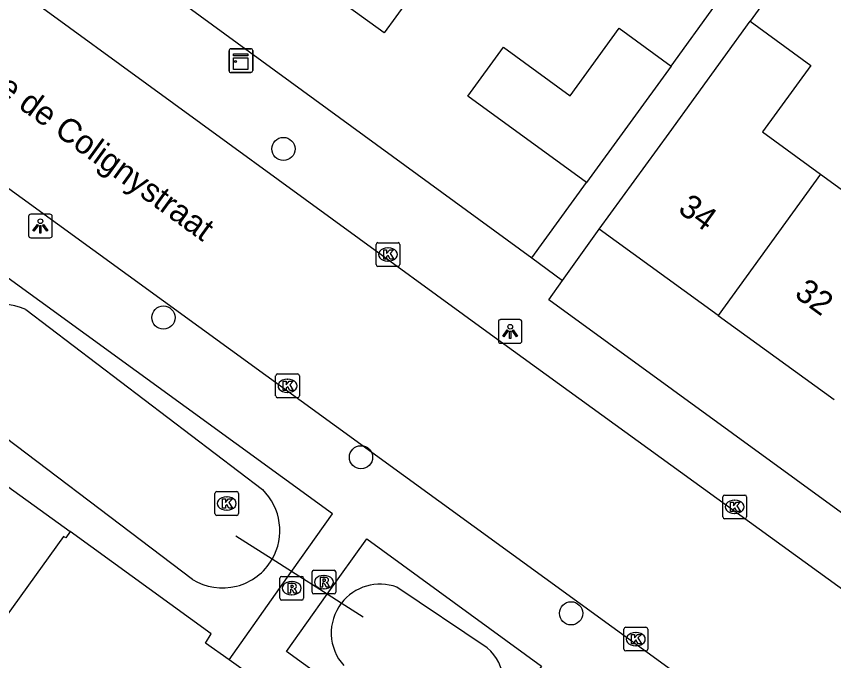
# Model space of a CAD drawing. Extents: x 159675 to 160530, y 382179 to 382901.
# Drawn here: x 160066.08 to 160100.56, y 382498.01 to 382525.17 of the extents above; entities that cross this region are included whole.
import ezdxf

# ---------------------------------------------------------------- set-up
doc = ezdxf.new("R2010")
doc.units = 0
for name, color, linetype in [('IMGEO_Boom', 7, 'Continuous'), ('IMGEO_Duiker', 7, 'Continuous'), ('IMGEO_Groenvoorziening', 7, 'Continuous'), ('IMGEO_Kast', 7, 'Continuous'), ('IMGEO_Kolk', 7, 'Continuous'), ('IMGEO_Lichtpunt', 7, 'Continuous'), ('IMGEO_Openbare_ruimte_label', 7, 'Continuous'), ('IMGEO_Pand', 7, 'Continuous'), ('IMGEO_Pand_nummerreeks', 7, 'Continuous'), ('IMGEO_Rijbaan_lokaal_open', 7, 'Continuous'), ('IMGEO_Rioolput', 7, 'Continuous'), ('IMGEO_Voetpad_open', 7, 'Continuous'), ('IMGEO_Waterloop', 7, 'Continuous')]:
    doc.layers.add(name, color=color, linetype=linetype)

msp = doc.modelspace()

# ---------------------------------------------------------------- linework, layer by layer
at = {"layer": 'IMGEO_Boom'}
for centre in [(160077.349, 382519.584), (160072.286, 382512.476), (160080.62, 382506.587), (160089.484, 382500.008)]:
    msp.add_circle(centre, 0.489, dxfattribs=at)
at = {"layer": 'IMGEO_Duiker'}
msp.add_lwpolyline([(160080.718, 382499.843), (160079.79, 382500.433), (160079.195, 382500.811), (160077.687, 382501.769), (160076.871, 382502.286), (160075.343, 382503.258)], dxfattribs=at)
at = {"layer": 'IMGEO_Groenvoorziening'}
msp.add_lwpolyline([(160075.053, 382498.052), (160074.062, 382498.749), (160074.3, 382499.148), (160068.355, 382503.451)], dxfattribs=at)
at = {"layer": 'IMGEO_Kast'}
for p, q in [((160075.052, 382522.883), (160075.052, 382523.724)), ((160075.052, 382523.724), (160075.052, 382522.883)), ((160075.127, 382523.808), (160075.968, 382523.808)), ((160075.968, 382523.808), (160075.127, 382523.808)), ((160076.052, 382523.733), (160076.052, 382522.892)), ((160076.052, 382522.892), (160076.052, 382523.733)), ((160075.977, 382522.808), (160075.136, 382522.808)), ((160075.136, 382522.808), (160075.977, 382522.808))]:
    msp.add_line(p, q, dxfattribs=at)
for points in [[(160075.247, 382523.598), (160075.847, 382523.598), (160075.847, 382523.513), (160075.247, 382523.513), (160075.247, 382523.598)], [(160075.247, 382523.423), (160075.847, 382523.423), (160075.847, 382522.934), (160075.247, 382522.934), (160075.247, 382523.423)]]:
    msp.add_lwpolyline(points, dxfattribs=at)
msp.add_circle((160075.331, 382523.272), 0.0377, dxfattribs=at)
for centre, start, end in [((160075.13, 382523.73), 92.4484, 184.2845), ((160075.13, 382523.73), 92.4484, 184.2845), ((160075.974, 382523.73), 2.4484, 94.2845), ((160075.974, 382523.73), 2.4484, 94.2845), ((160075.13, 382522.886), 182.4484, 274.2845), ((160075.13, 382522.886), 182.4484, 274.2845), ((160075.974, 382522.886), 272.4484, 4.2845), ((160075.974, 382522.886), 272.4484, 4.2845)]:
    msp.add_arc(centre, 0.0779, start, end, dxfattribs=at)
at = {"layer": 'IMGEO_Kolk'}
for p, q in [((160081.258, 382514.708), (160081.258, 382515.56)), ((160081.333, 382515.634), (160082.185, 382515.634)), ((160081.746, 382515.414), (160081.771, 382515.414)), ((160082.259, 382515.56), (160082.259, 382514.708)), ((160081.769, 382514.854), (160081.744, 382514.854)), ((160082.185, 382514.634), (160081.333, 382514.634)), ((160077.02, 382509.172), (160077.02, 382510.024)), ((160077.095, 382510.098), (160077.947, 382510.098)), ((160078.021, 382510.024), (160078.021, 382509.172)), ((160077.508, 382509.878), (160077.533, 382509.878)), ((160077.531, 382509.318), (160077.506, 382509.318)), ((160077.947, 382509.098), (160077.095, 382509.098)), ((160074.457, 382504.212), (160074.457, 382505.064)), ((160074.532, 382505.138), (160075.384, 382505.138)), ((160075.458, 382505.064), (160075.458, 382504.212)), ((160074.945, 382504.918), (160074.97, 382504.918)), ((160095.883, 382504.07), (160095.883, 382504.922)), ((160095.958, 382504.996), (160096.81, 382504.996)), ((160096.371, 382504.776), (160096.396, 382504.776)), ((160096.884, 382504.922), (160096.884, 382504.07)), ((160075.384, 382504.138), (160074.532, 382504.138)), ((160074.968, 382504.358), (160074.943, 382504.358)), ((160096.394, 382504.216), (160096.369, 382504.216)), ((160096.81, 382503.996), (160095.958, 382503.996)), ((160091.712, 382498.495), (160091.712, 382499.347)), ((160091.787, 382499.421), (160092.639, 382499.421)), ((160092.2, 382499.201), (160092.225, 382499.201)), ((160092.713, 382499.347), (160092.713, 382498.495)), ((160092.223, 382498.641), (160092.198, 382498.641)), ((160092.639, 382498.421), (160091.787, 382498.421))]:
    msp.add_line(p, q, dxfattribs=at)
for points in [[(160081.258, 382514.708), (160081.258, 382515.56)], [(160081.333, 382515.634), (160082.185, 382515.634)], [(160082.259, 382515.56), (160082.259, 382514.708)], [(160081.579, 382515.334), (160081.702, 382515.334), (160081.702, 382515.183), (160081.832, 382515.334), (160081.996, 382515.334), (160081.85, 382515.183), (160082.003, 382514.934), (160081.851, 382514.934), (160081.766, 382515.098), (160081.702, 382515.031), (160081.702, 382514.934), (160081.579, 382514.934), (160081.579, 382515.334)], [(160082.185, 382514.634), (160081.333, 382514.634)], [(160077.02, 382509.172), (160077.02, 382510.024)], [(160077.095, 382510.098), (160077.947, 382510.098)], [(160078.021, 382510.024), (160078.021, 382509.172)], [(160077.341, 382509.798), (160077.464, 382509.798), (160077.464, 382509.647), (160077.594, 382509.798), (160077.758, 382509.798), (160077.612, 382509.647), (160077.765, 382509.398), (160077.613, 382509.398), (160077.528, 382509.562), (160077.464, 382509.495), (160077.464, 382509.398), (160077.341, 382509.398), (160077.341, 382509.798)], [(160077.947, 382509.098), (160077.095, 382509.098)], [(160074.457, 382504.212), (160074.457, 382505.064)], [(160074.532, 382505.138), (160075.384, 382505.138)], [(160075.458, 382505.064), (160075.458, 382504.212)], [(160074.778, 382504.838), (160074.901, 382504.838), (160074.901, 382504.687), (160075.031, 382504.838), (160075.195, 382504.838), (160075.049, 382504.687), (160075.202, 382504.438), (160075.05, 382504.438), (160074.965, 382504.602), (160074.901, 382504.535), (160074.901, 382504.438), (160074.778, 382504.438), (160074.778, 382504.838)], [(160095.883, 382504.07), (160095.883, 382504.922)], [(160095.958, 382504.996), (160096.81, 382504.996)], [(160096.884, 382504.922), (160096.884, 382504.07)], [(160096.204, 382504.696), (160096.327, 382504.696), (160096.327, 382504.545), (160096.457, 382504.696), (160096.621, 382504.696), (160096.475, 382504.545), (160096.628, 382504.296), (160096.476, 382504.296), (160096.391, 382504.46), (160096.327, 382504.393), (160096.327, 382504.296), (160096.204, 382504.296), (160096.204, 382504.696)], [(160075.384, 382504.138), (160074.532, 382504.138)], [(160096.81, 382503.996), (160095.958, 382503.996)], [(160091.712, 382498.495), (160091.712, 382499.347)], [(160091.787, 382499.421), (160092.639, 382499.421)], [(160092.713, 382499.347), (160092.713, 382498.495)], [(160092.033, 382499.121), (160092.156, 382499.121), (160092.156, 382498.97), (160092.286, 382499.121), (160092.45, 382499.121), (160092.304, 382498.97), (160092.457, 382498.721), (160092.305, 382498.721), (160092.22, 382498.885), (160092.156, 382498.818), (160092.156, 382498.721), (160092.033, 382498.721), (160092.033, 382499.121)], [(160092.639, 382498.421), (160091.787, 382498.421)]]:
    msp.add_lwpolyline(points, dxfattribs=at)
for centre, start, end in [((160081.335, 382515.558), 91.552, 178.448), ((160081.335, 382515.558), 91.552, 178.448), ((160082.183, 382515.558), 1.552, 88.448), ((160082.183, 382515.558), 1.552, 88.448), ((160081.335, 382514.71), 181.552, 268.448), ((160081.335, 382514.71), 181.552, 268.448), ((160082.183, 382514.71), 271.552, 358.448), ((160082.183, 382514.71), 271.552, 358.448), ((160077.097, 382510.022), 91.552, 178.448), ((160077.097, 382510.022), 91.552, 178.448), ((160077.945, 382510.022), 1.552, 88.448), ((160077.945, 382510.022), 1.552, 88.448), ((160077.097, 382509.174), 181.552, 268.448), ((160077.097, 382509.174), 181.552, 268.448), ((160077.945, 382509.174), 271.552, 358.448), ((160077.945, 382509.174), 271.552, 358.448), ((160074.534, 382505.062), 91.552, 178.448), ((160074.534, 382505.062), 91.552, 178.448), ((160075.382, 382505.062), 1.552, 88.448), ((160075.382, 382505.062), 1.552, 88.448), ((160095.96, 382504.92), 91.552, 178.448), ((160095.96, 382504.92), 91.552, 178.448), ((160096.808, 382504.92), 1.552, 88.448), ((160096.808, 382504.92), 1.552, 88.448), ((160074.534, 382504.214), 181.552, 268.448), ((160074.534, 382504.214), 181.552, 268.448), ((160075.382, 382504.214), 271.552, 358.448), ((160075.382, 382504.214), 271.552, 358.448), ((160095.96, 382504.072), 181.552, 268.448), ((160095.96, 382504.072), 181.552, 268.448), ((160096.808, 382504.072), 271.552, 358.448), ((160096.808, 382504.072), 271.552, 358.448), ((160091.789, 382499.345), 91.552, 178.448), ((160091.789, 382499.345), 91.552, 178.448), ((160092.637, 382499.345), 1.552, 88.448), ((160092.637, 382499.345), 1.552, 88.448), ((160091.789, 382498.497), 181.552, 268.448), ((160091.789, 382498.497), 181.552, 268.448), ((160092.637, 382498.497), 271.552, 358.448), ((160092.637, 382498.497), 271.552, 358.448)]:
    msp.add_arc(centre, 0.0765, start, end, dxfattribs=at)
for centre, major_axis, ratio, start_param, end_param in [((160081.745, 382515.134), (-0.387, 0.002), 0.722429, 4.712389, 7.853982), ((160081.77, 382515.134), (-0.39, 0.002), 0.717154, 1.570796, 4.712389), ((160077.507, 382509.598), (-0.387, 0.002), 0.722429, 4.712389, 7.853982), ((160077.532, 382509.598), (-0.39, 0.002), 0.717154, 1.570796, 4.712389), ((160074.944, 382504.638), (-0.387, 0.002), 0.722429, 4.712389, 7.853982), ((160074.969, 382504.638), (-0.39, 0.002), 0.717154, 1.570796, 4.712389), ((160096.37, 382504.496), (-0.387, 0.002), 0.722429, 4.712389, 7.853982), ((160096.395, 382504.496), (-0.39, 0.002), 0.717154, 1.570796, 4.712389), ((160092.199, 382498.921), (-0.387, 0.002), 0.722429, 4.712389, 7.853982), ((160092.224, 382498.921), (-0.39, 0.002), 0.717154, 1.570796, 4.712389)]:
    msp.add_ellipse(centre, major_axis=major_axis, ratio=ratio, start_param=start_param, end_param=end_param, dxfattribs=at)
at = {"layer": 'IMGEO_Lichtpunt'}
for p, q in [((160067.499, 382516.834), (160066.691, 382516.834)), ((160067.499, 382516.834), (160066.691, 382516.834)), ((160066.597, 382516.739), (160066.597, 382515.932)), ((160066.597, 382516.739), (160066.597, 382515.932)), ((160067.593, 382515.932), (160067.593, 382516.739)), ((160067.593, 382515.932), (160067.593, 382516.739)), ((160066.691, 382515.838), (160067.499, 382515.838)), ((160066.691, 382515.838), (160067.499, 382515.838)), ((160087.316, 382512.388), (160086.508, 382512.388)), ((160087.316, 382512.388), (160086.508, 382512.388)), ((160086.414, 382512.293), (160086.414, 382511.486)), ((160086.414, 382512.293), (160086.414, 382511.486)), ((160087.41, 382511.486), (160087.41, 382512.293)), ((160087.41, 382511.486), (160087.41, 382512.293)), ((160086.508, 382511.392), (160087.316, 382511.392)), ((160086.508, 382511.392), (160087.316, 382511.392))]:
    msp.add_line(p, q, dxfattribs=at)
for points in [[(160066.971, 382516.403), (160067.01, 382516.375), (160066.822, 382516.113), (160066.784, 382516.14), (160066.971, 382516.403)], [(160067.073, 382516.355), (160067.12, 382516.355), (160067.12, 382516.033), (160067.073, 382516.033), (160067.073, 382516.355)], [(160067.183, 382516.375), (160067.221, 382516.402), (160067.408, 382516.14), (160067.369, 382516.112), (160067.183, 382516.375)], [(160086.788, 382511.957), (160086.827, 382511.929), (160086.639, 382511.667), (160086.601, 382511.694), (160086.788, 382511.957)], [(160087, 382511.929), (160087.038, 382511.956), (160087.225, 382511.694), (160087.186, 382511.666), (160087, 382511.929)], [(160086.89, 382511.909), (160086.937, 382511.909), (160086.937, 382511.587), (160086.89, 382511.587), (160086.89, 382511.909)]]:
    msp.add_lwpolyline(points, dxfattribs=at)
for centre in [(160067.096, 382516.537), (160086.913, 382512.091)]:
    msp.add_circle(centre, 0.0994, dxfattribs=at)
for centre, start, end in [((160066.691, 382516.739), 90, 180), ((160066.691, 382516.739), 90, 180), ((160067.499, 382516.739), 0, 90), ((160067.499, 382516.739), 0, 90), ((160066.691, 382515.932), 180, 270), ((160066.691, 382515.932), 180, 270), ((160067.499, 382515.932), 270, 0), ((160067.499, 382515.932), 270, 360), ((160086.508, 382512.293), 90, 180), ((160086.508, 382512.293), 90, 180), ((160087.316, 382512.293), 0, 90), ((160087.316, 382512.293), 0, 90), ((160086.508, 382511.486), 180, 270), ((160086.508, 382511.486), 180, 270), ((160087.316, 382511.486), 270, 0), ((160087.316, 382511.486), 270, 360)]:
    msp.add_arc(centre, 0.0946, start, end, dxfattribs=at)
at = {"layer": 'IMGEO_Pand'}
for points in [[(160081.824, 382531.551), (160085.04, 382529.214), (160081.597, 382524.477), (160078.381, 382526.815), (160072.249, 382531.273), (160075.691, 382536.008)], [(160090.673, 382516.21), (160093.613, 382520.255), (160097.038, 382524.967)], [(160097.038, 382524.967), (160099.595, 382523.109), (160097.556, 382520.304), (160100.009, 382518.521)], [(160090.131, 382518.165), (160085.126, 382521.804), (160086.631, 382523.874), (160089.441, 382521.831), (160091.507, 382524.672), (160093.702, 382523.077)], [(160093.702, 382523.077), (160090.131, 382518.165)], [(160100.009, 382518.521), (160095.688, 382512.57)], [(160100.009, 382518.521), (160104.902, 382514.966)], [(160095.688, 382512.57), (160090.673, 382516.21)], [(160095.688, 382512.57), (160100.581, 382509.018)], [(160060.796, 382508.902), (160068.355, 382503.451)], [(160068.355, 382503.451), (160068.166, 382503.189), (160068.076, 382503.253), (160065.037, 382499.042), (160065.126, 382498.977), (160065.02, 382498.831)]]:
    msp.add_lwpolyline(points, dxfattribs=at)
at = {"layer": 'IMGEO_Rijbaan_lokaal_open'}
for points in [[(160065.761, 382526.548), (160066.041, 382526.373), (160086.083, 382511.782), (160148.312, 382466.705), (160171.029, 382450.249)], [(160161.419, 382448.379), (160135.135, 382467.543), (160061.99, 382520.627), (160061.728, 382520.822)]]:
    msp.add_lwpolyline(points, dxfattribs=at)
at = {"layer": 'IMGEO_Rioolput'}
for p, q in [((160078.555, 382500.899), (160078.555, 382501.751)), ((160078.63, 382501.825), (160079.482, 382501.825)), ((160079.556, 382501.751), (160079.556, 382500.899)), ((160077.198, 382500.641), (160077.198, 382501.493)), ((160077.273, 382501.567), (160078.125, 382501.567)), ((160077.686, 382501.347), (160077.711, 382501.347)), ((160078.199, 382501.493), (160078.199, 382500.641)), ((160079.043, 382501.605), (160079.068, 382501.605)), ((160079.066, 382501.045), (160079.041, 382501.045)), ((160077.709, 382500.787), (160077.684, 382500.787)), ((160079.482, 382500.825), (160078.63, 382500.825)), ((160078.125, 382500.567), (160077.273, 382500.567))]:
    msp.add_line(p, q, dxfattribs=at)
for points in [[(160078.555, 382500.899), (160078.555, 382501.751)], [(160078.63, 382501.825), (160079.482, 382501.825)], [(160079.556, 382501.751), (160079.556, 382500.899)], [(160077.198, 382500.641), (160077.198, 382501.493)], [(160077.273, 382501.567), (160078.125, 382501.567)], [(160078.199, 382501.493), (160078.199, 382500.641)], [(160079.144, 382501.523), (160078.892, 382501.525), (160078.892, 382501.125)], [(160078.892, 382501.125), (160079.016, 382501.125), (160079.016, 382501.287), (160079.027, 382501.287)], [(160079.07, 382501.444), (160079.016, 382501.444), (160079.016, 382501.363)], [(160079.016, 382501.363), (160079.068, 382501.363)], [(160077.787, 382501.265), (160077.535, 382501.267), (160077.535, 382500.867)], [(160077.535, 382500.867), (160077.659, 382500.867), (160077.659, 382501.029), (160077.67, 382501.029)], [(160077.713, 382501.186), (160077.659, 382501.186), (160077.659, 382501.105)], [(160077.659, 382501.105), (160077.711, 382501.105)], [(160077.717, 382501), (160077.788, 382500.867), (160077.928, 382500.867), (160077.863, 382500.993)], [(160079.074, 382501.258), (160079.145, 382501.125), (160079.285, 382501.125), (160079.22, 382501.251)], [(160079.482, 382500.825), (160078.63, 382500.825)], [(160078.125, 382500.567), (160077.273, 382500.567)]]:
    msp.add_lwpolyline(points, dxfattribs=at)
for centre, radius, start, end in [((160078.632, 382501.749), 0.0765, 91.552, 178.448), ((160078.632, 382501.749), 0.0765, 91.552, 178.448), ((160079.48, 382501.749), 0.0765, 1.552, 88.448), ((160079.48, 382501.749), 0.0765, 1.552, 88.448), ((160077.275, 382501.491), 0.0765, 91.552, 178.448), ((160077.275, 382501.491), 0.0765, 91.552, 178.448), ((160078.123, 382501.491), 0.0765, 1.552, 88.448), ((160078.123, 382501.491), 0.0765, 1.552, 88.448), ((160079.026, 382501.234), 0.0533, 26.0293, 88.6989), ((160079.052, 382501.552), 0.19, 274.7715, 282.9687), ((160079.076, 382501.348), 0.0964, 77.0061, 93.1865), ((160079.09, 382501.405), 0.0378, 276.6634, 79.6772), ((160079.143, 382501.413), 0.109, 350.3612, 89.416), ((160079.141, 382501.413), 0.112, 277.5842, 350.9817), ((160079.125, 382501.198), 0.108, 29.5134, 73.7905), ((160077.669, 382500.976), 0.0533, 26.0293, 88.6989), ((160077.695, 382501.294), 0.19, 274.7715, 282.9687), ((160077.719, 382501.09), 0.0964, 77.0061, 93.1865), ((160077.733, 382501.147), 0.0378, 276.6634, 79.6772), ((160077.786, 382501.155), 0.109, 350.3612, 89.416), ((160077.784, 382501.155), 0.112, 277.5842, 350.9817), ((160077.768, 382500.94), 0.108, 29.5134, 73.7905), ((160077.275, 382500.643), 0.0765, 181.552, 268.448), ((160077.275, 382500.643), 0.0765, 181.552, 268.448), ((160078.123, 382500.643), 0.0765, 271.552, 358.448), ((160078.123, 382500.643), 0.0765, 271.552, 358.448), ((160078.632, 382500.901), 0.0765, 181.552, 268.448), ((160078.632, 382500.901), 0.0765, 181.552, 268.448), ((160079.48, 382500.901), 0.0765, 271.552, 358.448), ((160079.48, 382500.901), 0.0765, 271.552, 358.448)]:
    msp.add_arc(centre, radius, start, end, dxfattribs=at)
for centre, major_axis, ratio, start_param, end_param in [((160077.685, 382501.067), (-0.387, 0.002), 0.722429, 4.712389, 7.853982), ((160077.71, 382501.067), (-0.39, 0.002), 0.717154, 1.570796, 4.712389), ((160079.042, 382501.325), (-0.387, 0.002), 0.722429, 4.712389, 7.853982), ((160079.067, 382501.325), (-0.39, 0.002), 0.717154, 1.570796, 4.712389)]:
    msp.add_ellipse(centre, major_axis=major_axis, ratio=ratio, start_param=start_param, end_param=end_param, dxfattribs=at)
at = {"layer": 'IMGEO_Voetpad_open'}
for points in [[(160103.961, 382534.26), (160103.851, 382534.341), (160097.038, 382524.967)], [(160066.763, 382530.365), (160087.821, 382514.988)], [(160093.702, 382523.077), (160095.576, 382525.656)], [(160087.821, 382514.988), (160090.131, 382518.165)], [(160089.124, 382514.036), (160090.673, 382516.21)], [(160087.821, 382514.988), (160089.124, 382514.036)], [(160075.053, 382498.052), (160077.687, 382501.769), (160077.73, 382501.83), (160079.416, 382504.209), (160064.955, 382514.699)], [(160125.171, 382491.169), (160124.011, 382489.563), (160122.995, 382488.155), (160106.723, 382500), (160088.55, 382513.229), (160089.124, 382514.036)], [(160086.553, 382495.476), (160084.81, 382493.086), (160077.472, 382498.404), (160079.195, 382500.811), (160080.871, 382503.152), (160088.236, 382497.783), (160086.553, 382495.476)], [(160077.341, 382496.414), (160075.053, 382498.052)]]:
    msp.add_lwpolyline(points, dxfattribs=at)
at = {"layer": 'IMGEO_Waterloop'}
for points in [[(160066.48, 382512.812), (160076.472, 382505.222)], [(160073.513, 382501.441), (160063.45, 382509.055)], [(160085.943, 382498.556), (160082.134, 382501.113)]]:
    msp.add_lwpolyline(points, dxfattribs=at)
for centre, radius, start, end in [((160065.455, 382510.537), 2.495, 65.7428, 151.9348), ((160074.782, 382503.497), 2.415, 329.891, 45.5871), ((160074.781, 382503.496), 2.415, 238.3264, 329.9226), ((160081.425, 382499.179), 2.06, 69.859, 142.4961), ((160081.423, 382499.18), 2.058, 142.4978, 222.0295), ((160084.619, 382497.018), 2.03, 320.7677, 49.2769)]:
    msp.add_arc(centre, radius, start, end, dxfattribs=at)

# ---------------------------------------------------------------- texts
at = {"layer": 'IMGEO_Openbare_ruimte_label'}
msp.add_text('Louise de Colignystraat', height=1, rotation=323.9895, dxfattribs=at).set_placement((160062.641, 382523.876))
at = {"layer": 'IMGEO_Pand_nummerreeks'}
for s, p in [('34', (160093.943, 382516.95)), ('32', (160098.858, 382513.382))]:
    msp.add_text(s, height=1, rotation=324.0254, dxfattribs=at).set_placement(p)

doc.saveas('drawing.dxf')
